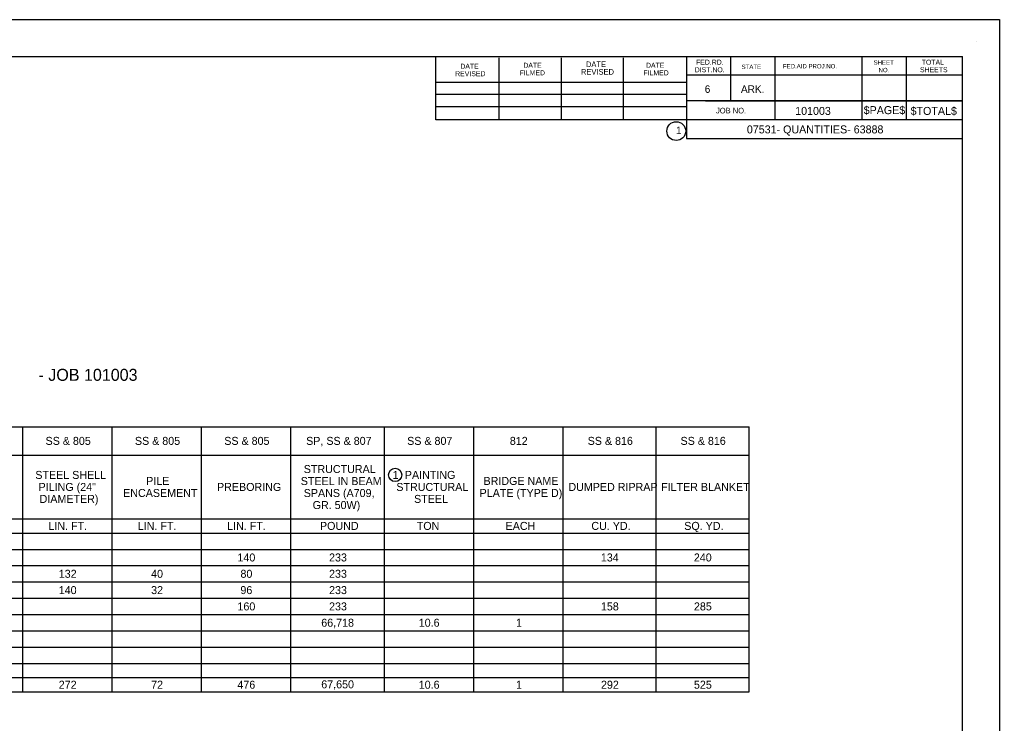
# Model space of a CAD drawing. Extents: x 188 to 14744886, y 129 to 1829278.
# Drawn here: x 206.58 to 221.88, y 139.51 to 150.51 of the extents above; entities that cross this region are included whole.
import ezdxf

# ---------------------------------------------------------------- set-up
doc = ezdxf.new("R2010")
doc.units = 0
for name, color, linetype in [('B_Copy In', 7, 'Continuous'), ('B_Text', 7, 'Continuous'), ('R_Border', 7, 'Continuous')]:
    doc.layers.add(name, color=color, linetype=linetype)

msp = doc.modelspace()

# ---------------------------------------------------------------- linework, layer by layer
at = {"layer": 'B_Text'}
for p, q in [((192.733, 144.151), (217.973, 144.151)), ((206.627, 140.007), (206.627, 144.151)), ((208.023, 140.007), (208.023, 144.151)), ((209.419, 140.007), (209.419, 144.151)), ((210.815, 140.007), (210.815, 144.151)), ((212.278, 140.007), (212.278, 144.151)), ((213.674, 140.007), (213.674, 144.151)), ((215.07, 140.007), (215.07, 144.151)), ((216.521, 140.007), (216.521, 144.151)), ((217.973, 140.007), (217.973, 144.151)), ((196.345, 143.708), (217.973, 143.708)), ((196.345, 142.711), (217.973, 142.711)), ((192.733, 142.489), (217.973, 142.489)), ((194.151, 142.234), (217.973, 142.234)), ((194.151, 141.98), (217.973, 141.98)), ((194.151, 141.725), (217.973, 141.725)), ((194.151, 141.47), (217.973, 141.47)), ((194.151, 141.215), (217.973, 141.215)), ((194.151, 140.96), (217.973, 140.96)), ((194.151, 140.705), (217.973, 140.705)), ((192.733, 140.451), (217.973, 140.451)), ((192.733, 140.229), (217.973, 140.229)), ((192.733, 140.007), (217.973, 140.007))]:
    msp.add_line(p, q, dxfattribs=at)
msp.add_circle((212.444, 143.397), 0.104, dxfattribs=at)
at = {"layer": 'R_Border'}
for p, q in [((221.525, 150.168), (221.525, 150.168)), ((189.399, 149.937), (221.306, 149.937)), ((213.08, 148.949), (213.08, 149.937)), ((214.066, 148.949), (214.066, 149.917)), ((215.042, 148.949), (215.042, 149.917)), ((216.01, 148.949), (216.01, 149.917)), ((216.996, 149.937), (216.996, 148.657)), ((217.68, 149.937), (217.68, 149.243)), ((218.374, 149.937), (218.374, 148.949)), ((219.732, 149.937), (219.732, 148.949)), ((220.426, 149.937), (220.426, 148.949)), ((221.306, 129.091), (221.306, 149.937)), ((221.306, 149.643), (216.996, 149.643)), ((221.306, 149.645), (221.306, 149.645)), ((213.08, 149.535), (216.996, 149.535)), ((213.08, 149.349), (216.996, 149.349)), ((221.306, 149.243), (216.996, 149.243)), ((217.292, 149.243), (221.306, 149.243)), ((213.08, 148.949), (213.08, 149.155)), ((213.08, 149.155), (216.996, 149.155)), ((221.306, 148.949), (213.08, 148.949)), ((216.996, 148.657), (221.306, 148.657)), ((216.996, 148.657), (221.306, 148.657))]:
    msp.add_line(p, q, dxfattribs=at)
msp.add_lwpolyline([(187.883, 150.514), (221.883, 150.514), (221.883, 128.514), (187.883, 128.514)], close=True, dxfattribs=at)
msp.add_circle((216.835, 148.771), 0.147, dxfattribs=at)

# ---------------------------------------------------------------- texts
at = {"layer": 'B_Copy In'}
msp.add_text('07531- QUANTITIES- 63888', height=0.1248, dxfattribs=at).set_placement((217.938, 148.735))
at = {"layer": 'B_Text'}
for s, height, p in [(' - JOB 101003', 0.1875, (206.802, 144.868)), ('SS & 805', 0.125, (206.982, 143.867)), ('SS & 805', 0.125, (208.378, 143.867)), ('SS & 805', 0.125, (209.774, 143.867)), ('SP, SS & 807', 0.125, (211.053, 143.867)), ('SS & 807', 0.125, (212.631, 143.867)), ('812', 0.125, (214.235, 143.867)), ('SS & 816', 0.125, (215.451, 143.867)), ('SS & 816', 0.125, (216.902, 143.867)), ('STEEL SHELL', 0.125, (206.822, 143.335)), (' STRUCTURAL', 0.125, (210.969, 143.427)), ('1', 0.125, (212.404, 143.335)), ('PAINTING', 0.125, (212.595, 143.335)), ('PILING (24"', 0.125, (206.873, 143.147)), ('PILE', 0.125, (208.554, 143.241)), ('PREBORING', 0.125, (209.661, 143.147)), ('STEEL IN BEAM', 0.125, (210.969, 143.239)), ('STRUCTURAL', 0.125, (212.462, 143.147)), ('BRIDGE NAME', 0.125, (213.824, 143.241)), ('ENCASEMENT', 0.125, (208.194, 143.053)), (' SPANS (A709,', 0.125, (210.969, 143.052)), ('PLATE (TYPE D)', 0.125, (213.763, 143.053)), ('DUMPED RIPRAP', 0.125, (215.15, 143.147)), ('FILTER BLANKET', 0.125, (216.598, 143.147)), ('DIAMETER)', 0.125, (206.889, 142.96)), ('    GR. 50W)', 0.125, (210.969, 142.864)), ('STEEL', 0.125, (212.739, 142.96)), ('LIN. FT.', 0.125, (207.027, 142.538)), ('LIN. FT.', 0.125, (208.423, 142.538)), ('LIN. FT.', 0.125, (209.819, 142.538)), ('POUND', 0.125, (211.269, 142.538)), ('TON', 0.125, (212.781, 142.538)), ('EACH', 0.125, (214.169, 142.538)), ('CU. YD.', 0.125, (215.509, 142.538)), ('SQ. YD.', 0.125, (216.96, 142.538)), ('140', 0.125, (209.98, 142.045)), ('233', 0.125, (211.411, 142.045)), ('134', 0.125, (215.657, 142.045)), ('240', 0.125, (217.11, 142.045)), ('132', 0.125, (207.188, 141.79)), ('40', 0.125, (208.631, 141.79)), ('80', 0.125, (210.027, 141.79)), ('233', 0.125, (211.411, 141.79)), ('140', 0.125, (207.188, 141.535)), ('32', 0.125, (208.631, 141.535)), ('96', 0.125, (210.026, 141.535)), ('233', 0.125, (211.411, 141.535)), ('160', 0.125, (209.98, 141.28)), ('233', 0.125, (211.411, 141.28)), ('158', 0.125, (215.658, 141.28)), ('285', 0.125, (217.111, 141.28)), ('66,718', 0.125, (211.289, 141.025)), ('10.6', 0.125, (212.812, 141.025)), ('1', 0.125, (214.332, 141.025)), ('272', 0.125, (207.188, 140.056)), ('72', 0.125, (208.631, 140.056)), ('476', 0.125, (209.979, 140.056)), ('67,650', 0.125, (211.289, 140.062)), ('10.6', 0.125, (212.812, 140.056)), ('1', 0.125, (214.332, 140.056)), ('292', 0.125, (215.659, 140.056)), ('525', 0.125, (217.111, 140.056))]:
    msp.add_text(s, height=height, dxfattribs=at).set_placement(p)
at = {"layer": 'R_Border'}
for s, height, p in [('DATE', 0.0879, (215.424, 149.771)), ('FED.RD.', 0.0782, (217.144, 149.809)), ('SHEET', 0.0684, (219.918, 149.809)), ('TOTAL', 0.0782, (220.67, 149.809)), ('REVISED', 0.0782, (213.381, 149.629)), ('DATE', 0.0782, (213.462, 149.746)), ('FILMED', 0.0782, (214.388, 149.643)), ('DATE', 0.0782, (214.446, 149.761)), ('REVISED', 0.0879, (215.346, 149.653)), ('FILMED', 0.0782, (216.322, 149.643)), ('DATE', 0.0782, (216.362, 149.761)), ('DIST.NO.', 0.0782, (217.124, 149.691)), ('STATE', 0.0684, (217.856, 149.741)), ('FED.AID PROJ.NO.', 0.0684, (218.502, 149.751)), ('NO.', 0.0684, (219.996, 149.691)), ('SHEETS', 0.0782, (220.642, 149.691)), ('6', 0.117, (217.28, 149.369)), ('ARK.', 0.1172, (217.846, 149.369)), ('JOB NO.', 0.0879, (217.456, 149.047)), ('101003', 0.1248, (218.693, 149.024)), ('$PAGE$', 0.1248, (219.763, 149.036)), ('$TOTAL$', 0.1248, (220.496, 149.024)), ('1', 0.117, (216.831, 148.724))]:
    msp.add_text(s, height=height, dxfattribs=at).set_placement(p)

doc.saveas('drawing.dxf')
